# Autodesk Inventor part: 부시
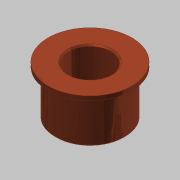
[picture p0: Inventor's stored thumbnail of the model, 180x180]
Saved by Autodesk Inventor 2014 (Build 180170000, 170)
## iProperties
Created: 2015-10
Part Number: 부시
Document SubType Name: Modeling
Designer: mdu
Density: 7.86 g/cm^3
Material: 강철, 연강
Mass: 364.706 g
Surface Area: 129.307 cm^2
Volume: 46.4003 cm^3
Appearance: Copper - Satin
Author: mdu
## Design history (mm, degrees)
sketch "스케치1"
  geometry: C1 r 31 at (0, 0) reference; C2 r 25 at (0, 0) reference; C3 r 30 at (0, 0) reference; 1 further point
  node "참조1"
  node "참조2"
  node "참조4"
extrude "돌출1" new body sketch "스케치1" distance "d0" = 3; taper "d1" = 0 deg
extrude "돌출2" join sketch "스케치1" distance "d2" = 35; taper "d3" = 0 deg
chamfer "모따기1" distance "d6" = 1; stored, may be unused: second distance "d7" = 2, angle "d8" = 45 deg
sketch "스케치3"
  geometry: C1 r 15 at (0, 0); 1 further point
  constraints: 1 centre point, 1 coincident
  dimensions: "d13" = 30 diameter of C1
extrude "돌출4" cut sketch "스케치3" stored distance "d14" = 10; taper "d15" = 0 deg
chamfer "모따기3" distance "d16" = 1; stored, may be unused: second distance "d17" = 2, angle "d18" = 45 deg
node "솔리드1"
